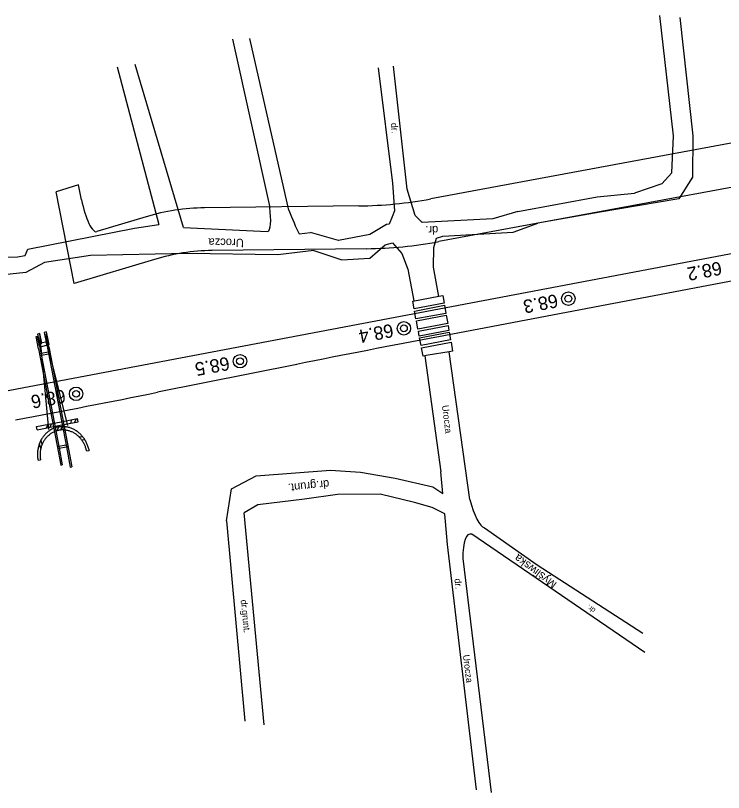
# Model space of a CAD drawing. Extents: x 6541740 to 6556805, y 5525233 to 5530361.
# Drawn here: x 6555448.4 to 6555554.3, y 5525773.6 to 5525889.9 of the extents above; entities that cross this region are included whole.
import ezdxf

# ---------------------------------------------------------------- set-up
doc = ezdxf.new("R2010")
doc.units = 0
for name, color, linetype in [('Default', 7, 'Continuous'), ('TOR_SCH-hektometry', 7, 'Continuous'), ('TOR_SCH-obiekty istniejace', 7, 'Continuous'), ('TOR_SCH-obiekty projektowane', 7, 'Continuous'), ('TOR_SCH-przejazdy+drogi istniejace', 7, 'Continuous'), ('TOR_SCH-przejazdy+drogi projektowane', 7, 'Continuous'), ('TOR_SCH-tory projektowane', 7, 'Continuous')]:
    doc.layers.add(name, color=color, linetype=linetype)

# ---------------------------------------------------------------- blocks, each defined once
blk = doc.blocks.new('4010_1')
at = {"layer": 'Default'}
for radius in [0.75, 0.375]:
    blk.add_circle((0, 0), radius, dxfattribs=at)

msp = doc.modelspace()

# ---------------------------------------------------------------- linework, layer by layer
at = {"layer": 'TOR_SCH-obiekty istniejace'}
for p, q in [((6555453.36, 5525827.95), (6555452.02, 5525842.32)), ((6555452.67, 5525842.48), (6555456.15, 5525828.55)), ((6555451.52, 5525828.42), (6555455.21, 5525829.12)), ((6555453.02, 5525828.19), (6555453.29, 5525828.75)), ((6555453.54, 5525828.29), (6555453.81, 5525828.85)), ((6555455.21, 5525829.12), (6555457.67, 5525829.59)), ((6555455.3, 5525828.63), (6555457.76, 5525829.1)), ((6555456.71, 5525828.89), (6555456.74, 5525829.41)), ((6555457.22, 5525829), (6555457.49, 5525829.56)), ((6555457.76, 5525829.1), (6555457.67, 5525829.59)), ((6555451.62, 5525827.92), (6555451.52, 5525828.42)), ((6555451.62, 5525827.92), (6555455.3, 5525828.63)), ((6555454.87, 5525828.33), (6555454.58, 5525827.79)), ((6555455.39, 5525828.41), (6555455.11, 5525827.86)), ((6555458.46, 5525826.85), (6555457.96, 5525826.83)), ((6555458.82, 5525826.39), (6555458.32, 5525826.38)), ((6555451.95, 5525825.8), (6555452.15, 5525825.17)), ((6555452.15, 5525826.34), (6555452.35, 5525825.7)), ((6555459.4, 5525824.77), (6555459.04, 5525824.7)), ((6555451.76, 5525823.35), (6555452.13, 5525823.41))]:
    msp.add_line(p, q, dxfattribs=at)
for points in [[(6555451.99, 5525840.8), (6555452.33, 5525840.88), (6555452.02, 5525842.32), (6555451.68, 5525842.24)], [(6555452.99, 5525841.04), (6555453.33, 5525841.12), (6555453.02, 5525842.56), (6555452.67, 5525842.48)], [(6555452.09, 5525840.34), (6555453.43, 5525840.66), (6555453.33, 5525841.12), (6555451.99, 5525840.8)]]:
    msp.add_lwpolyline(points, close=True, dxfattribs=at)
for points in [[(6555453.45, 5525827.77), (6555453.37, 5525827.71), (6555453.27, 5525827.64), (6555453.17, 5525827.56), (6555453.08, 5525827.48), (6555452.98, 5525827.39), (6555452.89, 5525827.3), (6555452.8, 5525827.21), (6555452.72, 5525827.12), (6555452.63, 5525827.02), (6555452.55, 5525826.92), (6555452.48, 5525826.81), (6555452.4, 5525826.71), (6555452.33, 5525826.6), (6555452.27, 5525826.49), (6555452.2, 5525826.37), (6555452.14, 5525826.25), (6555452.09, 5525826.13), (6555452.03, 5525826.01), (6555451.98, 5525825.89), (6555451.94, 5525825.77), (6555451.89, 5525825.64), (6555451.86, 5525825.51), (6555451.82, 5525825.38), (6555451.79, 5525825.25), (6555451.76, 5525825.12), (6555451.74, 5525824.98), (6555451.72, 5525824.85), (6555451.7, 5525824.71), (6555451.69, 5525824.58), (6555451.68, 5525824.44), (6555451.68, 5525824.31)], [(6555456.63, 5525827.67), (6555456.62, 5525827.68), (6555456.51, 5525827.71), (6555456.4, 5525827.75), (6555456.29, 5525827.78), (6555456.18, 5525827.81), (6555456.07, 5525827.83), (6555455.95, 5525827.85), (6555455.84, 5525827.86), (6555455.73, 5525827.87), (6555455.61, 5525827.88), (6555455.5, 5525827.88), (6555455.39, 5525827.88), (6555455.27, 5525827.88), (6555455.16, 5525827.87), (6555455.05, 5525827.86), (6555454.94, 5525827.84), (6555454.82, 5525827.82), (6555454.71, 5525827.79), (6555454.6, 5525827.76), (6555454.49, 5525827.73), (6555454.39, 5525827.7), (6555454.28, 5525827.66), (6555454.18, 5525827.61), (6555454.07, 5525827.56), (6555453.97, 5525827.51), (6555453.87, 5525827.46), (6555453.77, 5525827.4), (6555453.68, 5525827.34), (6555453.58, 5525827.27), (6555453.49, 5525827.21), (6555453.4, 5525827.13), (6555453.31, 5525827.06), (6555453.23, 5525826.98), (6555453.14, 5525826.9), (6555453.14, 5525826.9)], [(6555457.06, 5525827.99), (6555457.04, 5525828), (6555456.92, 5525828.06), (6555456.8, 5525828.11), (6555456.69, 5525828.15), (6555456.57, 5525828.19), (6555456.45, 5525828.23), (6555456.33, 5525828.26), (6555456.2, 5525828.29), (6555456.08, 5525828.32), (6555455.96, 5525828.34), (6555455.83, 5525828.36), (6555455.71, 5525828.37), (6555455.59, 5525828.38), (6555455.46, 5525828.38), (6555455.34, 5525828.38), (6555455.22, 5525828.37), (6555455.09, 5525828.36), (6555454.97, 5525828.35), (6555454.85, 5525828.33), (6555454.73, 5525828.31), (6555454.61, 5525828.28), (6555454.49, 5525828.25), (6555454.37, 5525828.21), (6555454.25, 5525828.18), (6555454.14, 5525828.13), (6555454.02, 5525828.08), (6555453.91, 5525828.03), (6555453.8, 5525827.98), (6555453.69, 5525827.92), (6555453.58, 5525827.85), (6555453.48, 5525827.79), (6555453.45, 5525827.77)], [(6555459.04, 5525824.7), (6555459.01, 5525824.82), (6555458.98, 5525824.94), (6555458.95, 5525825.05), (6555458.92, 5525825.17), (6555458.88, 5525825.28), (6555458.85, 5525825.39), (6555458.8, 5525825.5), (6555458.76, 5525825.61), (6555458.71, 5525825.72), (6555458.65, 5525825.83), (6555458.6, 5525825.93), (6555458.54, 5525826.03), (6555458.48, 5525826.13), (6555458.42, 5525826.23), (6555458.35, 5525826.33), (6555458.28, 5525826.43), (6555458.21, 5525826.52), (6555458.13, 5525826.61), (6555458.05, 5525826.7), (6555457.97, 5525826.78), (6555457.89, 5525826.87), (6555457.8, 5525826.95), (6555457.72, 5525827.03), (6555457.63, 5525827.1), (6555457.53, 5525827.17), (6555457.44, 5525827.24), (6555457.34, 5525827.31), (6555457.24, 5525827.37), (6555457.14, 5525827.43), (6555457.04, 5525827.49), (6555456.94, 5525827.54), (6555456.83, 5525827.59), (6555456.73, 5525827.63), (6555456.63, 5525827.67)], [(6555459.4, 5525824.77), (6555459.38, 5525824.91), (6555459.35, 5525825.04), (6555459.31, 5525825.18), (6555459.27, 5525825.31), (6555459.23, 5525825.44), (6555459.18, 5525825.57), (6555459.13, 5525825.7), (6555459.08, 5525825.82), (6555459.02, 5525825.95), (6555458.96, 5525826.07), (6555458.9, 5525826.19), (6555458.83, 5525826.31), (6555458.76, 5525826.42), (6555458.69, 5525826.54), (6555458.61, 5525826.65), (6555458.53, 5525826.75), (6555458.45, 5525826.86), (6555458.37, 5525826.96), (6555458.28, 5525827.06), (6555458.19, 5525827.16), (6555458.09, 5525827.25), (6555458, 5525827.34), (6555457.9, 5525827.43), (6555457.8, 5525827.52), (6555457.7, 5525827.6), (6555457.59, 5525827.67), (6555457.48, 5525827.75), (6555457.37, 5525827.82), (6555457.26, 5525827.88), (6555457.15, 5525827.94), (6555457.06, 5525827.99)], [(6555453.14, 5525826.9), (6555453.06, 5525826.82), (6555452.99, 5525826.73), (6555452.91, 5525826.64), (6555452.84, 5525826.55), (6555452.77, 5525826.46), (6555452.7, 5525826.36), (6555452.64, 5525826.26), (6555452.58, 5525826.16), (6555452.52, 5525826.06), (6555452.47, 5525825.95), (6555452.42, 5525825.85), (6555452.37, 5525825.74), (6555452.33, 5525825.63), (6555452.29, 5525825.52), (6555452.25, 5525825.41), (6555452.21, 5525825.29), (6555452.18, 5525825.18), (6555452.16, 5525825.06), (6555452.13, 5525824.95), (6555452.11, 5525824.83), (6555452.09, 5525824.72), (6555452.08, 5525824.6), (6555452.07, 5525824.48), (6555452.06, 5525824.36), (6555452.06, 5525824.24), (6555452.06, 5525824.12), (6555452.06, 5525824.01), (6555452.07, 5525823.89), (6555452.08, 5525823.77), (6555452.09, 5525823.65), (6555452.11, 5525823.53), (6555452.13, 5525823.41)], [(6555451.68, 5525824.31), (6555451.68, 5525824.31), (6555451.68, 5525824.17), (6555451.68, 5525824.03), (6555451.69, 5525823.9), (6555451.7, 5525823.76), (6555451.72, 5525823.62), (6555451.74, 5525823.49), (6555451.76, 5525823.35)]]:
    msp.add_lwpolyline(points, dxfattribs=at)
at = {"layer": 'TOR_SCH-obiekty projektowane'}
for p, q in [((6555451.83, 5525840.01), (6555451.48, 5525841.87)), ((6555451.98, 5525840.45), (6555451.7, 5525841.91)), ((6555453.09, 5525840.66), (6555452.81, 5525842.11)), ((6555453.38, 5525840.31), (6555453.03, 5525842.15)), ((6555451.98, 5525840.45), (6555454.9, 5525825.16)), ((6555453.09, 5525840.66), (6555456, 5525825.37)), ((6555451.83, 5525840.01), (6555454.6, 5525825.51)), ((6555451.97, 5525839.32), (6555453.52, 5525839.61)), ((6555452.02, 5525839.02), (6555453.57, 5525839.31)), ((6555453.38, 5525840.31), (6555456.15, 5525825.8)), ((6555454.6, 5525825.51), (6555455.15, 5525822.64)), ((6555454.62, 5525825.42), (6555456.17, 5525825.71)), ((6555454.68, 5525825.12), (6555456.22, 5525825.41)), ((6555456, 5525825.37), (6555456.58, 5525822.33)), ((6555456.15, 5525825.8), (6555456.8, 5525822.37)), ((6555454.9, 5525825.16), (6555455.37, 5525822.68)), ((6555455.15, 5525822.64), (6555455.37, 5525822.68)), ((6555456.58, 5525822.33), (6555456.8, 5525822.37))]:
    msp.add_line(p, q, dxfattribs=at)
for points in [[(6555451.48, 5525841.87), (6555451.7, 5525841.91)], [(6555452.81, 5525842.11), (6555453.03, 5525842.15)], [(6555456.69, 5525831), (6555456.69, 5525831)]]:
    msp.add_lwpolyline(points, dxfattribs=at)
at = {"layer": 'TOR_SCH-przejazdy+drogi istniejace'}
for p, q in [((6555546.79, 5525871.89), (6555544.74, 5525889.89)), ((6555547.74, 5525889.58), (6555549.71, 5525871.87)), ((6555480.84, 5525886.38), (6555486.41, 5525861.16)), ((6555489.28, 5525860.75), (6555483.46, 5525886.45)), ((6555463.59, 5525882.24), (6555469.83, 5525858.64)), ((6555473.49, 5525858.17), (6555466.3, 5525882.57)), ((6555546.55, 5525866.36), (6555546.79, 5525871.89)), ((6555549.71, 5525871.87), (6555549.67, 5525865.71)), ((6555545.04, 5525864.69), (6555546.55, 5525866.36)), ((6555549.67, 5525865.71), (6555549.52, 5525865.47)), ((6555545.04, 5525864.69), (6555540.95, 5525863.32)), ((6555450.23, 5525854.95), (6555466.18, 5525858.09)), ((6555466.18, 5525858.09), (6555469.83, 5525858.64)), ((6555473.49, 5525858.17), (6555486.1, 5525857.57)), ((6555490.83, 5525857.23), (6555492.5, 5525857.43)), ((6555449.85, 5525853.97), (6555450.23, 5525854.95)), ((6555474.09, 5525854.31), (6555459.61, 5525853.98)), ((6555487.64, 5525854.1), (6555474.09, 5525854.31)), ((6555492.99, 5525854.72), (6555487.64, 5525854.1)), ((6555445.67, 5525853.7), (6555448.71, 5525853.77)), ((6555448.71, 5525853.77), (6555449.85, 5525853.97)), ((6555459.61, 5525853.98), (6555452.7, 5525852.92)), ((6555452.7, 5525852.92), (6555449.93, 5525851.46)), ((6555449.93, 5525851.46), (6555429.74, 5525849.25)), ((6555512.29, 5525818.39), (6555511.99, 5525821.61)), ((6555485.59, 5525783.76), (6555482.6, 5525815.5)), ((6555513.01, 5525810.74), (6555512.58, 5525815.32)), ((6555479.94, 5525814.27), (6555482.69, 5525784.3)), ((6555518.52, 5525813.25), (6555526.43, 5525807.73)), ((6555542.54, 5525794.61), (6555516.62, 5525812.29)), ((6555517.36, 5525774.05), (6555513.01, 5525810.74)), ((6555515.3, 5525808.63), (6555519.52, 5525773.65)), ((6555526.43, 5525807.73), (6555542.23, 5525797.47))]:
    msp.add_line(p, q, dxfattribs=at)
for points in [[(6555523.53, 5525860.55), (6555519.76, 5525859.48), (6555509.22, 5525858.91), (6555508.18, 5525859.99), (6555506.95, 5525863.93), (6555504.93, 5525882.31)], [(6555502.63, 5525882.06), (6555504.77, 5525864.81), (6555505.06, 5525860.68), (6555504.73, 5525859.75), (6555504.27, 5525858.66), (6555504.27, 5525858.66), (6555503.9, 5525858.61), (6555501.37, 5525857.14), (6555496.69, 5525856.22), (6555492.5, 5525857.43)], [(6555549.67, 5525865.71), (6555547.59, 5525862.47), (6555535.82, 5525860.47), (6555526.49, 5525858.85)], [(6555523.53, 5525860.55), (6555535.41, 5525862.76), (6555540.95, 5525863.32)], [(6555511.73, 5525847.87), (6555510.89, 5525852.24), (6555510.96, 5525855.17), (6555511.36, 5525856.58), (6555512.31, 5525856.86), (6555522.82, 5525857.49), (6555525.18, 5525858.35), (6555526.49, 5525858.85)], [(6555492.99, 5525854.72), (6555497.21, 5525853.33), (6555501.4, 5525853.58), (6555503.66, 5525855.57), (6555504.77, 5525855.88), (6555506.17, 5525854.28), (6555507.07, 5525851.92), (6555507.98, 5525847.21)], [(6555516.33, 5525817.49), (6555513.23, 5525839.56)], [(6555509.59, 5525839), (6555511.99, 5525821.61)], [(6555479.94, 5525814.27), (6555480.68, 5525819.1), (6555480.68, 5525819.1), (6555484.4, 5525821.03), (6555484.4, 5525821.03), (6555495.52, 5525821.88), (6555499.97, 5525821.57), (6555505.19, 5525820.69), (6555510.79, 5525819.39), (6555512.29, 5525818.39)], [(6555512.58, 5525815.32), (6555510.72, 5525816.29), (6555508.05, 5525817.03), (6555502.92, 5525818.26), (6555496.53, 5525818.22), (6555491.63, 5525817.55), (6555484.63, 5525816.7), (6555482.6, 5525815.5)]]:
    msp.add_lwpolyline(points, dxfattribs=at)
for points in [[(6555512.48, 5525846.86), (6555508.01, 5525846.02), (6555507.8, 5525847.14), (6555511.73, 5525847.88), (6555512.28, 5525847.99)], [(6555508.07, 5525845.68), (6555512.54, 5525846.54), (6555512.76, 5525845.33), (6555508.29, 5525844.52)], [(6555508.35, 5525844.22), (6555512.81, 5525845.05), (6555513.03, 5525843.81), (6555508.58, 5525842.95)], [(6555508.64, 5525842.65), (6555513.09, 5525843.52), (6555513.22, 5525842.78), (6555508.78, 5525841.93)], [(6555508.83, 5525841.66), (6555513.27, 5525842.5), (6555513.47, 5525841.39), (6555509.04, 5525840.54)], [(6555509.11, 5525840.15), (6555513.54, 5525841), (6555513.77, 5525839.67), (6555513.23, 5525839.56), (6555510.11, 5525839.1), (6555509.34, 5525838.95)]]:
    msp.add_lwpolyline(points, close=True, dxfattribs=at)
for centre, major_axis, start_param, end_param in [((6555485.31, 5525861.56), (-0.76, 4), 3.174142, 4.563279), ((6555491.14, 5525873.16), (-3.79, 20), 2.19201, 2.443498), ((6555517.51, 5525819.61), (-1.21, 6.37), 1.861313, 3.021578), ((6555517.86, 5525804.13), (-1.55, 8.18), 6.138507, 7.225759)]:
    msp.add_ellipse(centre, major_axis=major_axis, ratio=0.25, start_param=start_param, end_param=end_param, dxfattribs=at)
at = {"layer": 'TOR_SCH-przejazdy+drogi projektowane'}
for p, q in [((6555592.39, 5525877.64), (6555510.5, 5525862.45)), ((6555593.6, 5525871.26), (6555511.7, 5525856.06)), ((6555457.83, 5525864.54), (6555454.46, 5525863.53)), ((6555458.27, 5525862.33), (6555457.83, 5525864.54)), ((6555457.16, 5525849.8), (6555454.46, 5525863.53)), ((6555499.75, 5525861.4), (6555476.67, 5525861.12)), ((6555467.92, 5525859.78), (6555460.54, 5525857.56)), ((6555500.89, 5525855.01), (6555477.81, 5525854.72)), ((6555469.17, 5525853.4), (6555457.16, 5525849.8))]:
    msp.add_line(p, q, dxfattribs=at)
for centre, major_axis, start_param, end_param in [((6555325.1, 5526841.81), (-185.63, 979.31), 3.097441, 3.140618), ((6555459.53, 5525862.71), (0.98, -5.16), 4.738599, 6.309396), ((6555564.85, 5525366.12), (-93.72, 494.45), 6.239034, 6.309396), ((6555325.1, 5526841.81), (-186.84, 985.7), 3.097441, 3.140618), ((6555564.85, 5525366.12), (-92.51, 488.06), 6.239034, 6.309396)]:
    msp.add_ellipse(centre, major_axis=major_axis, ratio=0.25, start_param=start_param, end_param=end_param, dxfattribs=at)
at = {"layer": 'TOR_SCH-tory projektowane'}
for p, q in [((6555661.88, 5525874.43), (6555417.84, 5525828.17)), ((6555662.57, 5525870.44), (6555511.67, 5525841.84)), ((6555490.45, 5525837.7), (6555469.61, 5525833.52))]:
    msp.add_line(p, q, dxfattribs=at)
for centre, start_param, end_param in [((6561648.16, 5493468.3), 6.283185, 6.28581), ((6549311.9, 5558202.92), 3.141593, 3.144217)]:
    msp.add_ellipse(centre, major_axis=(-6136.5, 32373.54), ratio=0.25, start_param=start_param, end_param=end_param, dxfattribs=at)

# ---------------------------------------------------------------- block references
at = {"layer": 'TOR_SCH-hektometry', "xscale": 1.345963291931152, "yscale": 1.345963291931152}
for p in [(6555531.08, 5525847.53), (6555506.48, 5525843.09), (6555481.97, 5525838.17), (6555457.45, 5525833.29)]:
    msp.add_blockref('4010_1', p, dxfattribs=at)

# ---------------------------------------------------------------- texts
at = {"layer": 'TOR_SCH-hektometry'}
for s, p in [('68.2', (6555553.82, 5525853.12)), ('68.3', (6555529.31, 5525848.24)), ('68.4', (6555504.7, 5525843.79)), ('68.5', (6555480.2, 5525838.87)), ('68.6', (6555455.67, 5525833.99))]:
    msp.add_text(s, height=2, rotation=190.7691, dxfattribs=at).set_placement(p)
at = {"layer": 'TOR_SCH-przejazdy+drogi istniejace'}
for s, height, rotation, p in [('dr.', 1, 276.3962, (6555504.51, 5525873.78)), ('dr.', 1.249, 181.0854, (6555511.61, 5525858.42)), ('Urocza', 1.249, 179.0688, (6555482.54, 5525856.48)), ('Urocza', 1, 277.2089, (6555512.17, 5525831.54)), ('dr.grunt.', 1.245, 185.7091, (6555495.26, 5525820.42)), ('Myśliwska', 1.208, 143.0906, (6555529.44, 5525804.98)), ('dr.', 1, 276.7675, (6555514.03, 5525805.6)), ('dr.grunt.', 1, 275.7138, (6555482.06, 5525802.44)), ('dr.', 0.788, 144.2597, (6555535.22, 5525801.07)), ('Urocza', 1, 276.8671, (6555515.31, 5525794.21))]:
    msp.add_text(s, height=height, rotation=rotation, dxfattribs=at).set_placement(p)

doc.saveas('drawing.dxf')
